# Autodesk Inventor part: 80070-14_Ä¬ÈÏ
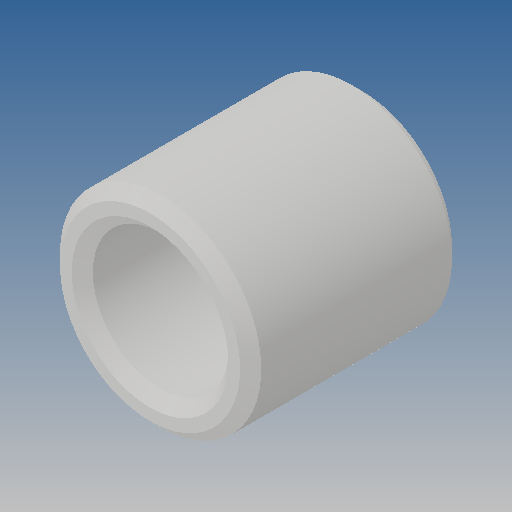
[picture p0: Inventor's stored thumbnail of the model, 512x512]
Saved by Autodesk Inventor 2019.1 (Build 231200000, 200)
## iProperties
Created: 2010-06
Part Number: 80070-14_Ä¬ÈÏ
Material: Ogólny
Document SubType Name: Modeling
Designer: CADENGINEERING4
Density: 1 g/cm^3
Appearance: Domyślna
Author: CADENGINEERING4
Revision Number: ÈÎºÎ
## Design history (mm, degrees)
feature "NONE"
node "Bryła1"
